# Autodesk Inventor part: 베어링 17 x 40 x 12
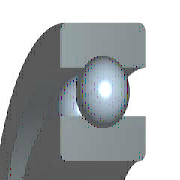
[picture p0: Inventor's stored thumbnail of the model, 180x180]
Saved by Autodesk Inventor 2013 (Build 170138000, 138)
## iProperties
IsCustomPart: 1
Created: 2012-02
Part Number: 베어링 17 x 40 x 12
Material: 강철, 연강
Description: 깊은 그루브 볼 베어링
Document SubType Name: Modeling
Standard: KS B 2023
Designer: mduedu
Standards Organization: KS
Language: ko-KR
Size Designation: 6203 - 17 x 40 x 12
Categories: <MemberInstance><Categories><Category DisplayName="샤프트 부품" InternalName="7f7aeb1f-a693-4053-b835-cee3144e0d98" Mnemonic="SHFT"><Category DisplayName="베어링" Inter
Density: 1 g/cm^3
Author: mduedu
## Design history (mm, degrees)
sketch "스케치" dims "d0" = 5.98 (= -0.26 x WD + 0.26 x BD)
  geometry: L1 (3.01, 14.25)-(8.99, 14.25); L2 (6, 14.25)-(6, 11.26); L3 (6, 14.25)-(6, 17.24); L4 (3.778, 12.249)-(0, 12.249); L5 (0, 8.5)-(12, 8.5); L6 (3.778, 16.251)-(0, 16.251); L7 (0, 20)-(12, 20); L8 (12, 8.5)-(12, 12.249); L9 (8.222, 12.249)-(12, 12.249); L10 (8.222, 16.251)-(12, 16.251); L11 (12, 20)-(12, 16.251); L12 (-1.4, 0)-(8.4, 0) reference; L13 (0, -0.3)-(0, 5.3) reference
  constraints: 22 end point, 4 point on line, 2 collinear, 2 perpendicular, 2 symmetric about line, 1 midpoint, 1 parallel, 14 other
  dimensions: "d9" = 17 diameter of L5 L12 (= WD); "d11" = 40 diameter of L7 L12 (= BD); "d12" = 12 distance between parallel lines of L8 L13 (= KB); "d13" = 24.498 diameter of L9 L12 (= 0.326 x BD + 0.674 x WD)
revolve "본체" stored, may be unused: angle "d6" = 90 deg
revolve "볼" stored, may be unused: angle "d7" = 90 deg
pattern_circular "IDS_ARRAYBALL[SIMPL:T]" dims angle "d3" = 360 deg
body "Solid1"
fillet "모깎기1" dims "d1" = 0.6 (= KRS)
other parameters: "WD" = 17 [user parameter; used in 5 equation terms], "BD" = 40 [user parameter; used in 5 equation terms], "KB" = 12 [user parameter; used in 1 equation term], "KRS" = 0.6 [user parameter; used in 1 equation term], "d4" = 0, "d5" = 0, "d8" = 0, "d14" = 0, "d15" = 0, "BBA" = 0 [user parameter], "BC0" = 4750000 [user parameter], "BC" = 9560000 [user parameter], "WR" = 8.5 (= 0.5 x WD) [user parameter]
